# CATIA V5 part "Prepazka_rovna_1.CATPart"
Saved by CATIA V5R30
Part number: Prepazka_rovna_1
Definition: E 21000_12_125__l_cut_to_length_80_1
Nomenclature: E 21000_12_125__l_cut_to_length_80_1
Source: Unknown
Description: PART-E 21000_12_125__l_cut_to_length_80_1-DESC
Bounding box of the stored display mesh (mm): x -6 to 6, y -6 to 6, z 0 to 88
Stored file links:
  E:\Bakalarka\Model\Forma_v7\Prepazka_rovna_1.CATPart
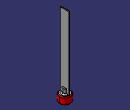
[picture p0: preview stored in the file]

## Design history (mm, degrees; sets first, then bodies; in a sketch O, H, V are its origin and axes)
Body1 "E 21000_12_125__l_cut_to_length_80" (main body)
  Solid1: solid without history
